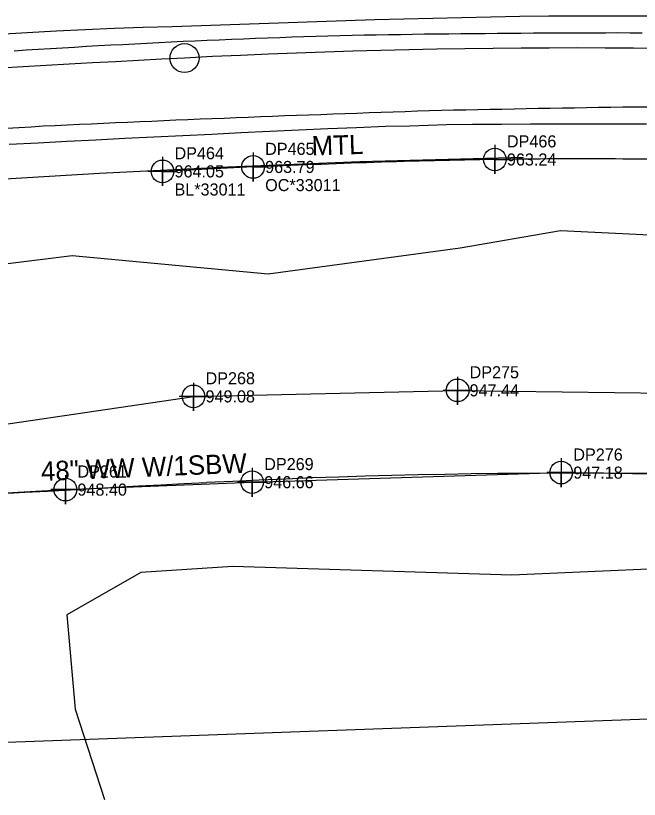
# Model space of a CAD drawing. Extents: x 1182322 to 1186765, y 572295 to 575411.
# Drawn here: x 1185012.8 to 1185141.8, y 573657.5 to 573819.7 of the extents above; entities that cross this region are included whole.
import ezdxf

# ---------------------------------------------------------------- set-up
doc = ezdxf.new("R2010")
doc.units = 0
for name, color, linetype in [('COGO Default Chain', 7, 'Continuous'), ('Exist Guardrail', 7, 'Continuous'), ('Exist Guardrail Cogo Comment', 7, 'Continuous'), ('Exist Guardrail Cogo Elevation', 7, 'Continuous'), ('Exist Guardrail Cogo Number', 7, 'Continuous'), ('Exist Guardrail Cogo Point CELL', 7, 'Continuous'), ('Exist Guardrail Text', 7, 'Continuous'), ('Exist Horizontal Alignment', 7, 'Continuous'), ('Exist Horizontal Alignment Point', 7, 'Continuous'), ('Exist Other Culture Fence Line', 7, 'Continuous'), ('Exist Other Culture Fence Line Cogo Elevation', 7, 'Continuous'), ('Exist Other Culture Fence Line Cogo Number', 7, 'Continuous'), ('Exist Other Culture Fence Line Cogo Point CELL', 7, 'Continuous'), ('Exist Other Culture Fence Line Text', 7, 'Continuous'), ('Exist Right of Way Line', 7, 'Continuous'), ('Exist Roads EOP', 7, 'Continuous'), ('Exist Roads EOT', 7, 'Continuous'), ('Exist Utilities Telephone UG Conduit SUE LOS B', 7, 'Continuous'), ('Exist Utilities Telephone UG Conduit SUE LOS B Cogo Elevation', 7, 'Continuous'), ('Exist Utilities Telephone UG Conduit SUE LOS B Cogo Number', 7, 'Continuous'), ('Exist Utilities Telephone UG Conduit SUE LOS B Cogo Point CELL', 7, 'Continuous'), ('Exist Vegetation Woods Line', 7, 'Continuous'), ('Sheet Layout Plan Border', 7, 'Continuous')]:
    doc.layers.add(name, color=color, linetype=linetype)

msp = doc.modelspace()

# ---------------------------------------------------------------- linework, layer by layer
at = {"layer": 'COGO Default Chain'}
for centre, radius, start, end in [((1185128.8, 572235.35), 1577.62, 86.1973, 92.94509), ((1185332.16, 568282.65), 5535.54, 92.94509, 94.52634)]:
    msp.add_arc(centre, radius, start, end, dxfattribs=at)
at = {"layer": 'Exist Guardrail'}
msp.add_line((1185061.93, 573788.34), (1185043.18, 573787.43), dxfattribs=at)
msp.add_lwpolyline([(1185117.88, 573790.32), (1185084.03, 573789.38), (1185056.74, 573788.27), (1185030.15, 573786.97), (1185008.24, 573785.66), (1184984.92, 573784.41), (1184958.75, 573782.63), (1184939.11, 573781.23), (1184913.28, 573779.4), (1184890.07, 573777.86), (1184868.74, 573776.28), (1184850.59, 573775.01), (1184830.97, 573773.4), (1184808.46, 573771.76), (1184780.42, 573769.59), (1184746.98, 573767.19), (1184724.28, 573765.46), (1184696.48, 573763.55), (1184670.09, 573761.5), (1184642.01, 573759.29), (1184614.6, 573757.31), (1184594.84, 573755.66)], dxfattribs=at)
msp.add_spline([(1185594.93, 573734.55), (1185552.15, 573743.92), (1185503.35, 573753.48), (1185460.44, 573761.12), (1185417.11, 573768.48), (1185367.38, 573775.86), (1185317.73, 573781.22), (1185267.96, 573784.75), (1185211.84, 573788.21), (1185161.85, 573789.69), (1185111.95, 573789.89), (1185061.93, 573788.34)], degree=3, dxfattribs=at)
at = {"layer": 'Exist Guardrail Cogo Point CELL'}
for points in [[(1185111.95, 573792.89), (1185111.95, 573786.89), (1185111.95, 573789.89), (1185114.95, 573789.89), (1185108.95, 573789.89)], [(1185061.93, 573791.34), (1185061.93, 573785.34), (1185061.93, 573788.34), (1185064.93, 573788.34), (1185058.93, 573788.34)], [(1185043.18, 573790.43), (1185043.18, 573784.43), (1185043.18, 573787.43), (1185046.18, 573787.43), (1185040.18, 573787.43)]]:
    msp.add_lwpolyline(points, dxfattribs=at)
for centre in [(1185111.95, 573789.89), (1185043.18, 573787.43), (1185061.93, 573788.34)]:
    msp.add_circle(centre, 2.34, dxfattribs=at)
at = {"layer": 'Exist Horizontal Alignment'}
for centre, radius, start, end in [((1185128.8, 572235.35), 1577.62, 86.1973, 92.94509), ((1185332.16, 568282.65), 5535.54, 92.94509, 94.52634)]:
    msp.add_arc(centre, radius, start, end, dxfattribs=at)
at = {"layer": 'Exist Horizontal Alignment Point'}
msp.add_circle((1185047.75, 573810.88), 3, dxfattribs=at)
at = {"layer": 'Exist Other Culture Fence Line'}
msp.add_lwpolyline([(1184699.34, 573697.51), (1184773.78, 573703.02), (1184848.65, 573709.06), (1184900.84, 573713.11), (1184965.64, 573718.36), (1185023.1, 573721.56), (1185061.74, 573723.1), (1185125.69, 573725.08), (1185204.48, 573724.02), (1185248.27, 573721.81), (1185300.17, 573718.11), (1185350.66, 573712.74), (1185422.95, 573702.8), (1185464.84, 573695.68), (1185533.29, 573681.7), (1185567.96, 573674.22), (1185634.32, 573659.17)], dxfattribs=at)
at = {"layer": 'Exist Other Culture Fence Line Cogo Point CELL'}
for points in [[(1185125.69, 573728.08), (1185125.69, 573722.08), (1185125.69, 573725.08), (1185128.69, 573725.08), (1185122.69, 573725.08)], [(1185061.74, 573726.1), (1185061.74, 573720.1), (1185061.74, 573723.1), (1185064.74, 573723.1), (1185058.74, 573723.1)], [(1185023.1, 573724.56), (1185023.1, 573718.56), (1185023.1, 573721.56), (1185026.1, 573721.56), (1185020.1, 573721.56)]]:
    msp.add_lwpolyline(points, dxfattribs=at)
for centre in [(1185125.69, 573725.08), (1185061.74, 573723.1), (1185023.1, 573721.56)]:
    msp.add_circle(centre, 2.34, dxfattribs=at)
at = {"layer": 'Exist Right of Way Line'}
for centre, radius, start, end in [((1185128.8, 572235.35), 1489.62, 86.1973, 92.94509), ((1185332.16, 568282.65), 5447.54, 92.94509, 94.52634)]:
    msp.add_arc(centre, radius, start, end, dxfattribs=at)
at = {"layer": 'Exist Roads EOP'}
for points in [[(1185009.21, 573815.85), (1185015.2, 573816.17), (1185021.19, 573816.49), (1185027.18, 573816.8), (1185033.18, 573817.04), (1185039.18, 573817.24), (1185045.17, 573817.44), (1185051.17, 573817.64), (1185057.16, 573817.84), (1185063.16, 573818.04), (1185069.16, 573818.25), (1185075.15, 573818.45), (1185081.15, 573818.65), (1185087.15, 573818.83), (1185093.14, 573818.98), (1185099.14, 573819.13), (1185105.14, 573819.28), (1185111.14, 573819.43), (1185117.14, 573819.58), (1185123.14, 573819.65), (1185129.13, 573819.65), (1185135.13, 573819.65), (1185141.13, 573819.65), (1185147.13, 573819.65)], [(1185143.35, 573797.22), (1185137.35, 573797.22), (1185131.35, 573797.22), (1185125.35, 573797.2), (1185119.35, 573797.19), (1185113.35, 573797.15), (1185107.34, 573797.11), (1185101.98, 573797.03), (1185094.39, 573796.76), (1185089.35, 573796.7), (1185083.36, 573796.45), (1185077.37, 573796.2), (1185071.37, 573795.95), (1185065.38, 573795.67), (1185059.39, 573795.38), (1185053.39, 573795.08), (1185047.4, 573794.79), (1185041.41, 573794.5), (1185035.42, 573794.2), (1185029.42, 573793.89), (1185023.43, 573793.59), (1185017.44, 573793.29), (1185011.45, 573792.97)]]:
    msp.add_lwpolyline(points, dxfattribs=at)
at = {"layer": 'Exist Roads EOT'}
for points in [[(1185142.42, 573816.05), (1185139.92, 573816.06), (1185137.42, 573816.07), (1185134.92, 573816.06), (1185132.42, 573816.06), (1185129.92, 573816.05), (1185127.42, 573816.04), (1185124.92, 573816.03), (1185122.42, 573816.02), (1185119.92, 573816.01), (1185117.42, 573815.99), (1185114.92, 573815.97), (1185112.42, 573815.94), (1185109.92, 573815.92), (1185107.42, 573815.9), (1185104.92, 573815.87), (1185102.42, 573815.85), (1185099.92, 573815.83), (1185097.42, 573815.8), (1185094.92, 573815.76), (1185092.43, 573815.72), (1185089.93, 573815.68), (1185087.43, 573815.64), (1185084.93, 573815.59), (1185082.43, 573815.55), (1185079.93, 573815.5), (1185077.43, 573815.44), (1185074.93, 573815.35), (1185072.43, 573815.27), (1185069.93, 573815.18), (1185067.44, 573815.09), (1185064.94, 573814.99), (1185062.44, 573814.9), (1185059.94, 573814.8), (1185057.44, 573814.7), (1185054.95, 573814.6), (1185052.45, 573814.51), (1185049.95, 573814.41), (1185047.45, 573814.3), (1185044.96, 573814.17), (1185042.46, 573814.04), (1185039.96, 573813.91), (1185037.47, 573813.78), (1185034.97, 573813.65), (1185032.47, 573813.52), (1185029.98, 573813.39), (1185027.48, 573813.25), (1185024.99, 573813.09), (1185022.49, 573812.93), (1185020, 573812.78), (1185017.5, 573812.62), (1185015, 573812.48), (1185012.51, 573812.33)], [(1185143.42, 573800.7), (1185140.92, 573800.7), (1185138.42, 573800.69), (1185135.92, 573800.66), (1185133.42, 573800.63), (1185130.92, 573800.58), (1185128.42, 573800.53), (1185125.92, 573800.48), (1185123.42, 573800.44), (1185120.92, 573800.41), (1185118.42, 573800.36), (1185115.92, 573800.3), (1185113.42, 573800.25), (1185110.92, 573800.2), (1185108.42, 573800.15), (1185105.92, 573800.11), (1185103.42, 573800.07), (1185100.92, 573800.01), (1185098.43, 573799.93), (1185095.93, 573799.86), (1185093.43, 573799.78), (1185090.93, 573799.7), (1185088.43, 573799.61), (1185085.93, 573799.52), (1185083.43, 573799.43), (1185080.94, 573799.34), (1185078.44, 573799.25), (1185075.94, 573799.16), (1185073.44, 573799.07), (1185070.94, 573798.98), (1185068.45, 573798.9), (1185065.95, 573798.81), (1185063.45, 573798.71), (1185060.95, 573798.61), (1185058.45, 573798.51), (1185055.96, 573798.4), (1185053.46, 573798.3), (1185050.96, 573798.2), (1185048.46, 573798.11), (1185045.97, 573798), (1185043.47, 573797.88), (1185040.97, 573797.78), (1185038.47, 573797.67), (1185035.98, 573797.56), (1185033.48, 573797.46), (1185030.98, 573797.35), (1185028.48, 573797.23), (1185025.99, 573797.11), (1185023.49, 573796.99), (1185020.99, 573796.87), (1185018.5, 573796.75), (1185016, 573796.61), (1185013.5, 573796.46), (1185011.01, 573796.32)]]:
    msp.add_lwpolyline(points, dxfattribs=at)
at = {"layer": 'Exist Utilities Telephone UG Conduit SUE LOS B'}
msp.add_lwpolyline([(1184705.2, 573717.51), (1184761.61, 573719.92), (1184808.75, 573719.14), (1184855.63, 573717.48), (1184899.38, 573717.73), (1184947.65, 573726.76), (1184989.59, 573731.99), (1185049.6, 573740.86), (1185104.23, 573742.11), (1185147.54, 573741.49), (1185190.99, 573738.17), (1185243.67, 573733.83), (1185296.19, 573730.81), (1185343.76, 573727.54), (1185391.61, 573722.1), (1185423.08, 573716.53), (1185467.66, 573711.88), (1185536.39, 573704.97), (1185583.2, 573696.39), (1185626.44, 573682.88)], dxfattribs=at)
at = {"layer": 'Exist Utilities Telephone UG Conduit SUE LOS B Cogo Point CELL'}
for points in [[(1185104.22, 573744.92), (1185104.25, 573739.11), (1185104.23, 573742.11), (1185107.25, 573742.11), (1185101.25, 573742.11)], [(1185049.59, 573743.68), (1185049.62, 573737.86), (1185049.6, 573740.86), (1185052.62, 573740.86), (1185046.62, 573740.86)]]:
    msp.add_lwpolyline(points, dxfattribs=at)
for centre in [(1185104.25, 573742.11), (1185049.62, 573740.86)]:
    msp.add_circle(centre, 2.34, dxfattribs=at)
at = {"layer": 'Exist Vegetation Woods Line'}
for points in [[(1184575.02, 573729.05), (1184597.15, 573732.62), (1184637.97, 573736.65), (1184706.19, 573743.8), (1184765.1, 573753.09), (1184813.5, 573755.42), (1184873.05, 573752.61), (1184920.1, 573754.56), (1184952.91, 573761.14), (1185024.52, 573770.05), (1185065.05, 573766.23), (1185104.79, 573771.63), (1185125.52, 573775.21), (1185166.8, 573773.18), (1185213.51, 573768.99), (1185272.49, 573771.32), (1185349.48, 573766.46), (1185397.23, 573756.66)], [(1185359.01, 573702.12), (1185320.37, 573707.45), (1185270.98, 573712.83), (1185217.04, 573710.02), (1185162.54, 573705.94), (1185115.44, 573703.83), (1185057.71, 573705.66), (1185038.72, 573704.43), (1185023.43, 573695.62), (1185025.14, 573676.09), (1185031.21, 573657.46)]]:
    msp.add_lwpolyline(points, dxfattribs=at)
at = {"layer": 'Sheet Layout Plan Border'}
msp.add_line((1184830.48, 573662.79), (1185374.39, 573682.41), dxfattribs=at)

# ---------------------------------------------------------------- texts
at = {"layer": 'Exist Guardrail Cogo Comment'}
for s, p in [('BL*33011', (1185045.68, 573782.43)), ('OC*33011', (1185064.43, 573783.34))]:
    msp.add_text(s, height=2.5, dxfattribs=at).set_placement(p)
at = {"layer": 'Exist Guardrail Cogo Elevation'}
for s, p in [('963.24', (1185114.45, 573788.64)), ('963.79', (1185064.43, 573787.09)), ('964.05', (1185045.68, 573786.18))]:
    msp.add_text(s, height=2.5, dxfattribs=at).set_placement(p)
at = {"layer": 'Exist Guardrail Cogo Number'}
for s, p in [('DP466', (1185114.45, 573792.39)), ('DP465', (1185064.43, 573790.84)), ('DP464', (1185045.68, 573789.93))]:
    msp.add_text(s, height=2.5, dxfattribs=at).set_placement(p)
at = {"layer": 'Exist Guardrail Text'}
msp.add_text('MTL', height=4, rotation=1.811, dxfattribs=at).set_placement((1185074.11, 573790.71))
at = {"layer": 'Exist Other Culture Fence Line Cogo Elevation'}
for s, p in [('947.18', (1185128.19, 573723.83)), ('946.66', (1185064.24, 573721.85)), ('948.40', (1185025.6, 573720.31))]:
    msp.add_text(s, height=2.5, dxfattribs=at).set_placement(p)
at = {"layer": 'Exist Other Culture Fence Line Cogo Number'}
for s, p in [('DP276', (1185128.19, 573727.58)), ('DP269', (1185064.24, 573725.6)), ('DP261', (1185025.6, 573724.06))]:
    msp.add_text(s, height=2.5, dxfattribs=at).set_placement(p)
at = {"layer": 'Exist Other Culture Fence Line Text'}
msp.add_text('48" WW W/1SBW', height=4, rotation=2.2956, dxfattribs=at).set_placement((1185018.11, 573723.36))
at = {"layer": 'Exist Utilities Telephone UG Conduit SUE LOS B Cogo Elevation'}
for s, p in [('947.44', (1185106.73, 573740.86)), ('949.08', (1185052.1, 573739.61))]:
    msp.add_text(s, height=2.5, dxfattribs=at).set_placement(p)
at = {"layer": 'Exist Utilities Telephone UG Conduit SUE LOS B Cogo Number'}
for s, p in [('DP268', (1185052.1, 573743.36)), ('DP275', (1185106.73, 573744.61))]:
    msp.add_text(s, height=2.5, dxfattribs=at).set_placement(p)

doc.saveas('drawing.dxf')
